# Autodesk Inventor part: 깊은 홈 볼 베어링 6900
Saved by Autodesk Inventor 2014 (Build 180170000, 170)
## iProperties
Created: 2026-05
Part Number: 깊은 홈 볼 베어링 6900
Material: 일반
Document SubType Name: Modeling
Designer: dg
Density: 1 g/cm^3
Appearance: 기본값
Author: dg
Author: jhkim
Description: 깊은 그루브 볼 베어링
Creation Date: 2026-04-27
Sending System: Autodesk Inventor 2027
Preprocessor: ST-DEVELOPER v20.1
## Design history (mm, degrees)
node "깊은 홈 볼 베어링 69001"
body "Solid1"
node "Solid1_1"
node "Solid1_2"
node "Solid1_3"
node "Solid1_4"
node "Solid1_5"
node "Solid1_6"
node "Solid1_7"
node "Solid1_8"
node "Solid1_9"
node "기준1"
node "기준2"
node "기준3"
node "기준4"
node "기준5"
node "기준6"
node "기준7"
node "기준8"
node "기준9"
node "기준10"
